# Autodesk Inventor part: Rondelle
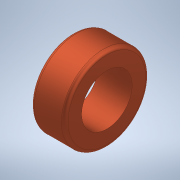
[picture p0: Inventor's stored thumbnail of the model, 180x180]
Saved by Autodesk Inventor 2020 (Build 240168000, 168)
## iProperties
Created: 2023-10
Part Number: Rondelle
Material: Cuivre
Document SubType Name: Modeling
Designer: bruno
Density: 8.94 g/cm^3
Appearance: Cuivre - Satiné
Author: bruno
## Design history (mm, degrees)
sketch "Esquisse1"
  geometry: C1 r 2.5 at (0, 0); C2 r 1.5 at (0, 0); 1 further point
  constraints: 2 centre point, 2 coincident
  dimensions: "d0" = 5 diameter of C1; "d1" = 3 diameter of C2
extrude "Extrusion1" new body sketch "Esquisse1" distance "d2" = 2; taper "d3" = 0 deg
fillet "Congé1" dims "d4" = 0.2
node "Solide1"
